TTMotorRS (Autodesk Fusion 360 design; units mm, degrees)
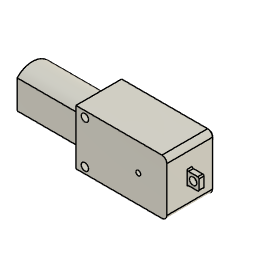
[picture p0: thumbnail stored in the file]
sketch "Sketch1" plane through (0, 0, 0) normal (0, 0, 1) x axis (1, 0, 0)
  line L1 (-64, 0) -> (-2, 0)
  line L2 (-64, 22.3) -> (-64, 0)
  line L3 (-2, 22.3) -> (-64, 22.3)
  line L4 (0, 2) -> (0, 20.3)
  line L5 (-37, 0) -> (-37, 22.3)
  line L6 (4.8, 13.65) -> (0, 13.65)
  line L7 (4.8, 8.65) -> (4.8, 13.65)
  line L8 (0, 8.65) -> (4.8, 8.65)
  line L9 (0, 13.65) -> (0, 8.65)
  line L10 (-11.6, 0) -> (-11.6, 22.3)
  line L11 (-2.35, 22.3) -> (-2.35, 19.815)
  line L12 (-2.35, 0) -> (-2.35, 2.485)
  line L13 (-9.6334, 13) -> (-13.5666, 13)
  line L14 (-9.6334, 9.3) -> (-13.5666, 9.3)
  line L15 (-64, 17.515) -> (-37, 17.515)
  line L16 (-64, 4.785) -> (-37, 4.785)
  line L17 (-53.8571, 17.515) -> (-53.8571, 22.3)
  line L18 (-53.8571, 0) -> (-53.8571, 4.785)
  line L19 (-22.85, 11.15) -> (-11.6, 11.15)
  circle C1 centre (2.4, 11.15) radius 1.5
  circle C2 centre (-11.6, 11.15) radius 2.7
  circle C3 centre (-2.35, 19.815) radius 1.5
  circle C4 centre (-2.35, 2.485) radius 1.5
  arc A1 centre (-2, 20.3) radius 2 clockwise from (-2, 22.3) to (0, 20.3)
  arc A2 centre (-2, 2) radius 2 clockwise from (0, 2) to (-2, 0)
  circle C5 centre (-11.6, 11.15) radius 0.975
  circle C6 centre (-22.85, 11.15) radius 2
  circle C7 centre (-33.35, 2.485) radius 1.5
  circle C8 centre (-33.35, 19.815) radius 1.5
  point P1 (0, 0)
  point P2 (0, 0)
  point P6 (-37, 22.3)
  point P7 (-37, 0)
  point P12 (0, 11.15)
  point P14 (-11.6, 22.3)
  point P16 (-11.6, 11.15)
  point P17 (-2.35, 19.815)
  point P19 (-2.35, 19.815)
  point P20 (-2.35, 22.3)
  point P18 (-2.35, 2.485)
  point P21 (-2.35, 2.485)
  point P22 (-2.35, 0)
  point P5 (0, 22.3)
  point P29 (-13.5666, 13)
  point P30 (-9.6334, 13)
  point P31 (-13.5666, 9.3)
  point P32 (-9.6334, 9.3)
  point P34 (-37, 17.515)
  point P35 (-64, 17.515)
  point P36 (-37, 4.785)
  point P37 (-64, 4.785)
  point P38 (-53.8571, 22.3)
  point P39 (-53.8571, 17.515)
  point P40 (-53.8571, 4.785)
  point P41 (-53.8571, 0)
  point P33 (-11.6, 11.15)
  point P42 (-11.6, 11.15)
  point P43 (-22.85, 11.15)
  point P44 (-22.85, 11.15)
  point P3 (-64, 0)
  point P8 (0, 13.65)
  point P9 (4.8, 13.65)
  point P11 (0, 8.65)
  point P13 (2.4, 11.15)
  point P45 (-33.35, 2.485)
  point P46 (-33.35, 19.815)
  horizontal L1
  vertical L2
  horizontal L3
  vertical L4
  coincident P1 P2
  coincident L3 P6
  coincident L1 P7
  perpendicular L1 L5
  horizontal L6
  vertical L7
  horizontal L8
  vertical L9
  midpoint L9 P12
  coincident L3 P14
  perpendicular L3 L10
  coincident L10 P16
  coincident P17 P19
  coincident L3 P20
  perpendicular L3 L11
  coincident P18 P21
  coincident L1 P22
  perpendicular L1 L12
  equal L11 L12
  collinear L11 L12
  coincident L4 P12
  coincident P5 L3
  coincident P5 L4
  tangent L3 A1
  tangent L4 A1
  coincident P2 L1
  coincident P2 L4
  tangent L1 A2
  tangent L4 A2
  coincident C2 P29
  coincident C2 P30
  perpendicular L10 L13
  coincident C2 P31
  coincident C2 P32
  perpendicular L10 L14
  equal L13 L14
  concentric C2 C5
  coincident L5 P34
  coincident L2 P35
  perpendicular L2 L15
  coincident L5 P36
  coincident L2 P37
  perpendicular L2 L16
  coincident L3 P38
  coincident L15 P39
  perpendicular L15 L17
  coincident L16 P40
  coincident L1 P41
  perpendicular L1 L18
  equal L17 L18
  coincident P33 P42
  perpendicular L10 L19
  coincident P43 P44
  dimension "d1" distance P2 P3 = 64
  dimension "d2" distance P2 P5 = 22.3
  dimension "d3" distance L4 L5 = 37
  dimension "d4" distance P8 P9 = 4.8
  dimension "d5" distance P8 P11 = 5
  dimension "d6" diameter C1 = 3
  dimension "d7" distance P13 L10 = 14
  dimension "d8" diameter C2 = 5.4
  dimension "d9" distance P17 P18 = 17.33
  dimension "d10" distance L10 L11 = 9.25
  dimension "d11" radius A1 = 2
  dimension "d12" radius A2 = 2
  dimension "d13" distance L13 L14 = 3.7
  dimension "d14" diameter C5 = 1.95
  dimension "d15" distance L15 L16 = 12.73
  dimension "d16" distance P42 P43 = 11.25
  dimension "d17" diameter C6 = 4
  dimension "d18" diameter C3 = 3
  dimension "d19" diameter C4 = 3
  dimension "d20" distance P45 P46 = 17.33
  dimension "d21" diameter C8 = 3
  dimension "d22" diameter C7 = 3
  dimension "d29" distance L1 L19 = 11.15
extrude "Extrude1" new body sketch "Sketch1" profile of L1 L3 L4 L5 L9 C2 C3 C4 A1 A2 C6 C7 C8 distance 9.3 (= "( 18.6 / 2 ) * 1 mm")
extrude "Extrude2" add sketch "Sketch1" profile of C2 L13 L14 distance 10
extrude "Extrude3" add sketch "Sketch1" profile of C2 L13 L14 C5 distance 18.3
sketch "Sketch2" plane through (-37, 0, 0) normal (-1, 0, 0) x axis (0, -1, 0)
  line L1 (0, 9.3) -> (0, -9.3)
  line L2 (-22.3, 9.3) -> (0, 9.3)
  line L3 (-22.3, -9.3) -> (-22.3, 9.3)
  line L4 (0, -9.3) -> (-22.3, -9.3)
  line L5 (-22.3, 0) -> (0, 0)
  line L6 (-5.3354, 6.2) -> (-16.9646, 6.2)
  line L7 (-5.3354, -6.2) -> (-16.9646, -6.2)
  circle C1 centre (-11.15, 0) radius 8.5
  point P8 (-11.15, 0)
  point P9 (-16.9646, 6.2)
  point P10 (-5.3354, 6.2)
  point P11 (-16.9646, -6.2)
  point P12 (-5.3354, -6.2)
  midpoint L5 P8
  coincident C1 P9
  coincident C1 P10
  parallel L5 L6
  symmetric L5 P9 P11
  symmetric L5 P10 P12
  dimension "d30" diameter C1 = 17
  dimension "d31" distance L5 L6 = 6.2
extrude "Extrude4" add sketch "Sketch2" profile of L5 C1 L6 L7 along normal blind 27
extrude "Extrude5" add sketch "Sketch1" profile of L4 L6 L7 L8 L9 C1 distance 1
extrude "Extrude6" add sketch "Sketch1" profile of C6 along normal blind 11.22 (= "9.30 mm + 1.92 mm")
extrude "Extrude7" add sketch "Sketch1" profile of C6 against normal blind 9.3
fillet "Fillet1" radius 0.5
move "Move1"
move "Move2"
delete_face "DeleteFace1"
delete_face "DeleteFace2"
